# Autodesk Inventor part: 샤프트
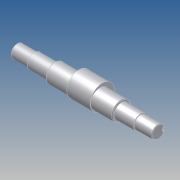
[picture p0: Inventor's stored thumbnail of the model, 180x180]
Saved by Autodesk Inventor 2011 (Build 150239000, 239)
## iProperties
Created: 2013-06
Part Number: 샤프트
Document SubType Name: Modeling
Designer: SeoGD™[esajin.kr]
Density: 1 g/cm^3
Author: SeoGD™[esajin.kr]
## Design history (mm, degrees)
sketch "스케치1"
  geometry: L1 (-20.5, -41.331)-(-20.5, 32.669) reference; L2 (7.5, -30.031)-(7.5, 21.369) reference; L3 (135.5, -30.331)-(135.5, 21.669) reference; L4 (121.5, 21.369)-(121.5, -30.031) reference; L5 (184.5, -4.331)-(-57.5, -4.331); L6 (184.5, -4.331)-(184.5, 6.669); L7 (154.5, 8.169)-(121.5, 8.169); L8 (121.5, 8.169)-(121.5, 11.669); L9 (121.5, 11.669)-(7.5, 11.669); L10 (7.5, 11.669)-(7.5, 8.169); L11 (7.5, 8.169)-(-27.5, 8.169); L12 (-27.5, 8.169)-(-27.5, 6.669); L13 (-27.5, 6.669)-(-57.5, 6.669); L14 (-57.5, 6.669)-(-57.5, -4.331); L15 (154.5, 8.169)-(154.5, 6.669); L16 (154.5, 6.669)-(184.5, 6.669); C1 r 32.5 at (64.5, -4.331) reference; 1 further point
  constraints: 24 end point, 8 perpendicular, 5 point on line, 3 parallel, 2 collinear
  dimensions: "d1" = 25 diameter of L11 L5; "d2" = 32 diameter of L9 L5; "d3" = 22 diameter of L13 L5; "d4" = 35 distance of L10.end L11.end; "d5" = 30 distance of L12.end L13.end; "d15" = 33 distance of L7.start L7.end; "d26" = 30 distance of L15.end L6.end
revolve "회전1" sketch "스케치1" stored, may be unused: angle "d6" = 90 deg
node "작업 평면1"
sketch "스케치2"
  geometry: C1 r 16 at (0, 0) reference; C2 r 16 at (0, 0) reference; C3 r 20.75 at (0, 4); C4 r 16 at (0, 0) reference; 1 further point
  constraints: 1 centre point, 1 vertical alignment
  dimensions: "d8" = 41.5 diameter of C3; "d25" = 4 distance of C3.centre C1.centre
extrude "돌출1" join sketch "스케치2" stored distance "d9" = 40; taper "d10" = 0 deg
chamfer "모따기1" distance "d11" = 1; stored, may be unused: second distance "d12" = 2, angle "d13" = 45 deg
node "작업 평면2"
sketch "스케치3"
  geometry: L1 (-15, -10)-(-15, 10) reference; L2 (-15, 3)-(0, 3); L3 (0, -3)-(-15, -3); A1 r 3 centre (0, 0) between (0, -3) and (0, 3); 2 further points
  constraints: 4 end point, 2 perpendicular, 2 point on circle, 2 point on line, 2 tangent, 1 centre point, 1 horizontal alignment, 1 midpoint
  dimensions: "d16" = 18 dimension on A1 L1; "d17" = 6 distance between parallel lines of L3 L2
extrude "돌출2" cut sketch "스케치3" distance "d18" = 3.5; taper "d19" = 0 deg
node "작업 평면3"
node "솔리드1"
mirror "대칭1"
node "참조1"
node "참조2"
node "참조3"
node "참조4"
node "참조5"
node "투영된 루프1"
